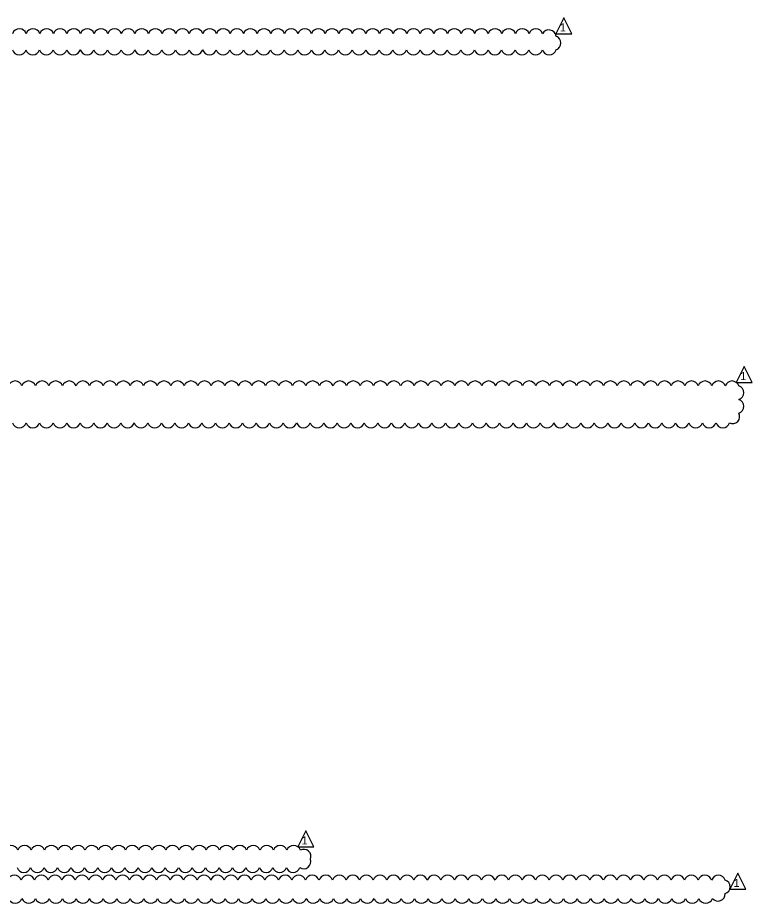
# Model space of a CAD drawing. Extents: x -156 to 77, y 0 to 24.
# Drawn here: x 64.1 to 76.95, y 1.25 to 16.74 of the extents above; entities that cross this region are included whole.
import ezdxf

# ---------------------------------------------------------------- set-up
doc = ezdxf.new("R2010")
doc.units = 0
doc.layers.add('SH_Text', color=7, linetype='Continuous')

msp = doc.modelspace()

# ---------------------------------------------------------------- linework, layer by layer
at = {"layer": 'SH_Text'}
for points in [[(73.654, 16.74), (73.514, 16.46), (73.794, 16.46)], [(76.807, 10.643), (76.667, 10.363), (76.947, 10.363)], [(69.139, 2.523), (68.999, 2.243), (69.279, 2.243)], [(76.692, 1.778), (76.552, 1.498), (76.832, 1.498)]]:
    msp.add_lwpolyline(points, close=True, dxfattribs=at)
for centre, radius, start, end in [((64.132, 16.423), 0.125, 17.5, 162.5), ((64.369, 16.423), 0.125, 17.5, 162.5), ((64.607, 16.423), 0.125, 17.5, 162.5), ((64.844, 16.423), 0.125, 17.5, 162.5), ((65.082, 16.423), 0.125, 17.5, 162.5), ((65.32, 16.423), 0.125, 17.5, 162.5), ((65.557, 16.423), 0.125, 17.5, 162.5), ((65.795, 16.423), 0.125, 17.5, 162.5), ((66.033, 16.423), 0.125, 17.5, 162.5), ((66.27, 16.423), 0.125, 17.5, 162.5), ((66.508, 16.423), 0.125, 17.5, 162.5), ((66.746, 16.423), 0.125, 17.5, 162.5), ((66.983, 16.423), 0.125, 17.5, 162.5), ((67.221, 16.423), 0.125, 17.5, 162.5), ((67.458, 16.423), 0.125, 17.5, 162.5), ((67.696, 16.423), 0.125, 17.5, 162.5), ((67.934, 16.423), 0.125, 17.5, 162.5), ((68.171, 16.423), 0.125, 17.5, 162.5), ((68.409, 16.423), 0.125, 17.5, 162.5), ((68.647, 16.423), 0.125, 17.5, 162.5), ((68.884, 16.423), 0.125, 17.5, 162.5), ((69.122, 16.423), 0.125, 17.5, 162.5), ((69.36, 16.423), 0.125, 17.5, 162.5), ((69.597, 16.423), 0.125, 17.5, 162.5), ((69.835, 16.423), 0.125, 17.5, 162.5), ((70.072, 16.423), 0.125, 17.5, 162.5), ((70.31, 16.423), 0.125, 17.5, 162.5), ((70.548, 16.423), 0.125, 17.5, 162.5), ((70.785, 16.423), 0.125, 17.5, 162.5), ((71.023, 16.423), 0.125, 17.5, 162.5), ((71.261, 16.423), 0.125, 17.5, 162.5), ((71.498, 16.423), 0.125, 17.5, 162.5), ((71.736, 16.423), 0.125, 17.5, 162.5), ((71.974, 16.423), 0.125, 17.5, 162.5), ((72.211, 16.423), 0.125, 17.5, 162.5), ((72.449, 16.423), 0.125, 17.5, 162.5), ((72.686, 16.423), 0.125, 17.5, 162.5), ((72.924, 16.423), 0.125, 17.5, 162.5), ((73.162, 16.423), 0.125, 17.5, 162.5), ((73.391, 16.402), 0.125, 7.2291, 152.2291), ((73.477, 16.299), 0.125, 287.5, 72.5), ((64.128, 16.217), 0.125, 197.5, 342.5), ((64.365, 16.217), 0.125, 197.5, 342.5), ((64.603, 16.217), 0.125, 197.5, 342.5), ((64.841, 16.217), 0.125, 197.5, 342.5), ((65.078, 16.217), 0.125, 197.5, 342.5), ((65.316, 16.217), 0.125, 197.5, 342.5), ((65.554, 16.217), 0.125, 197.5, 342.5), ((65.791, 16.217), 0.125, 197.5, 342.5), ((66.029, 16.217), 0.125, 197.5, 342.5), ((66.266, 16.217), 0.125, 197.5, 342.5), ((66.504, 16.217), 0.125, 197.5, 342.5), ((66.742, 16.217), 0.125, 197.5, 342.5), ((66.979, 16.217), 0.125, 197.5, 342.5), ((67.217, 16.217), 0.125, 197.5, 342.5), ((67.455, 16.217), 0.125, 197.5, 342.5), ((67.692, 16.217), 0.125, 197.5, 342.5), ((67.93, 16.217), 0.125, 197.5, 342.5), ((68.168, 16.217), 0.125, 197.5, 342.5), ((68.405, 16.217), 0.125, 197.5, 342.5), ((68.643, 16.217), 0.125, 197.5, 342.5), ((68.88, 16.217), 0.125, 197.5, 342.5), ((69.118, 16.217), 0.125, 197.5, 342.5), ((69.356, 16.217), 0.125, 197.5, 342.5), ((69.593, 16.217), 0.125, 197.5, 342.5), ((69.831, 16.217), 0.125, 197.5, 342.5), ((70.069, 16.217), 0.125, 197.5, 342.5), ((70.306, 16.217), 0.125, 197.5, 342.5), ((70.544, 16.217), 0.125, 197.5, 342.5), ((70.782, 16.217), 0.125, 197.5, 342.5), ((71.019, 16.217), 0.125, 197.5, 342.5), ((71.257, 16.217), 0.125, 197.5, 342.5), ((71.494, 16.217), 0.125, 197.5, 342.5), ((71.732, 16.217), 0.125, 197.5, 342.5), ((71.97, 16.217), 0.125, 197.5, 342.5), ((72.207, 16.217), 0.125, 197.5, 342.5), ((72.445, 16.217), 0.125, 197.5, 342.5), ((72.683, 16.217), 0.125, 197.5, 342.5), ((72.92, 16.217), 0.125, 197.5, 342.5), ((73.158, 16.217), 0.125, 197.5, 342.5), ((73.396, 16.217), 0.125, 197.5, 342.5), ((64.057, 10.263), 0.124, 17.5, 162.5), ((64.293, 10.263), 0.124, 17.5, 162.5), ((64.53, 10.263), 0.124, 17.5, 162.5), ((64.766, 10.263), 0.124, 17.5, 162.5), ((65.003, 10.263), 0.124, 17.5, 162.5), ((65.24, 10.263), 0.124, 17.5, 162.5), ((65.476, 10.263), 0.124, 17.5, 162.5), ((65.713, 10.263), 0.124, 17.5, 162.5), ((65.949, 10.263), 0.124, 17.5, 162.5), ((66.186, 10.263), 0.124, 17.5, 162.5), ((66.422, 10.263), 0.124, 17.5, 162.5), ((66.659, 10.263), 0.124, 17.5, 162.5), ((66.895, 10.263), 0.124, 17.5, 162.5), ((67.132, 10.263), 0.124, 17.5, 162.5), ((67.368, 10.263), 0.124, 17.5, 162.5), ((67.605, 10.263), 0.124, 17.5, 162.5), ((67.842, 10.263), 0.124, 17.5, 162.5), ((68.078, 10.263), 0.124, 17.5, 162.5), ((68.315, 10.263), 0.124, 17.5, 162.5), ((68.551, 10.263), 0.124, 17.5, 162.5), ((68.788, 10.263), 0.124, 17.5, 162.5), ((69.024, 10.263), 0.124, 17.5, 162.5), ((69.261, 10.263), 0.124, 17.5, 162.5), ((69.497, 10.263), 0.124, 17.5, 162.5), ((69.734, 10.263), 0.124, 17.5, 162.5), ((69.97, 10.263), 0.124, 17.5, 162.5), ((70.207, 10.263), 0.124, 17.5, 162.5), ((70.443, 10.263), 0.124, 17.5, 162.5), ((70.68, 10.263), 0.124, 17.5, 162.5), ((70.917, 10.263), 0.124, 17.5, 162.5), ((71.153, 10.263), 0.124, 17.5, 162.5), ((71.39, 10.263), 0.124, 17.5, 162.5), ((71.626, 10.263), 0.124, 17.5, 162.5), ((71.863, 10.263), 0.124, 17.5, 162.5), ((72.099, 10.263), 0.124, 17.5, 162.5), ((72.336, 10.263), 0.124, 17.5, 162.5), ((72.572, 10.263), 0.124, 17.5, 162.5), ((72.809, 10.263), 0.124, 17.5, 162.5), ((73.045, 10.263), 0.124, 17.5, 162.5), ((73.282, 10.263), 0.124, 17.5, 162.5), ((73.519, 10.263), 0.124, 17.5, 162.5), ((73.755, 10.263), 0.124, 17.5, 162.5), ((73.992, 10.263), 0.124, 17.5, 162.5), ((74.228, 10.263), 0.124, 17.5, 162.5), ((74.465, 10.263), 0.124, 17.5, 162.5), ((74.701, 10.263), 0.124, 17.5, 162.5), ((74.938, 10.263), 0.124, 17.5, 162.5), ((75.174, 10.263), 0.124, 17.5, 162.5), ((75.411, 10.263), 0.124, 17.5, 162.5), ((75.647, 10.263), 0.124, 17.5, 162.5), ((75.884, 10.263), 0.124, 17.5, 162.5), ((76.121, 10.263), 0.124, 17.5, 162.5), ((76.357, 10.263), 0.124, 17.5, 162.5), ((76.594, 10.263), 0.124, 17.5, 162.5), ((76.675, 10.182), 0.124, 287.5, 72.5), ((76.675, 9.945), 0.124, 287.5, 72.5), ((76.603, 9.767), 0.124, 243.9222, 28.9222), ((64.13, 9.693), 0.124, 197.5, 342.5), ((64.367, 9.693), 0.124, 197.5, 342.5), ((64.603, 9.693), 0.124, 197.5, 342.5), ((64.84, 9.693), 0.124, 197.5, 342.5), ((65.077, 9.693), 0.124, 197.5, 342.5), ((65.313, 9.693), 0.124, 197.5, 342.5), ((65.55, 9.693), 0.124, 197.5, 342.5), ((65.786, 9.693), 0.124, 197.5, 342.5), ((66.023, 9.693), 0.124, 197.5, 342.5), ((66.259, 9.693), 0.124, 197.5, 342.5), ((66.496, 9.693), 0.124, 197.5, 342.5), ((66.732, 9.693), 0.124, 197.5, 342.5), ((66.969, 9.693), 0.124, 197.5, 342.5), ((67.205, 9.693), 0.124, 197.5, 342.5), ((67.442, 9.693), 0.124, 197.5, 342.5), ((67.679, 9.693), 0.124, 197.5, 342.5), ((67.915, 9.693), 0.124, 197.5, 342.5), ((68.152, 9.693), 0.124, 197.5, 342.5), ((68.388, 9.693), 0.124, 197.5, 342.5), ((68.625, 9.693), 0.124, 197.5, 342.5), ((68.861, 9.693), 0.124, 197.5, 342.5), ((69.098, 9.693), 0.124, 197.5, 342.5), ((69.334, 9.693), 0.124, 197.5, 342.5), ((69.571, 9.693), 0.124, 197.5, 342.5), ((69.807, 9.693), 0.124, 197.5, 342.5), ((70.044, 9.693), 0.124, 197.5, 342.5), ((70.281, 9.693), 0.124, 197.5, 342.5), ((70.517, 9.693), 0.124, 197.5, 342.5), ((70.754, 9.693), 0.124, 197.5, 342.5), ((70.99, 9.693), 0.124, 197.5, 342.5), ((71.227, 9.693), 0.124, 197.5, 342.5), ((71.463, 9.693), 0.124, 197.5, 342.5), ((71.7, 9.693), 0.124, 197.5, 342.5), ((71.936, 9.693), 0.124, 197.5, 342.5), ((72.173, 9.693), 0.124, 197.5, 342.5), ((72.409, 9.693), 0.124, 197.5, 342.5), ((72.646, 9.693), 0.124, 197.5, 342.5), ((72.882, 9.693), 0.124, 197.5, 342.5), ((73.119, 9.693), 0.124, 197.5, 342.5), ((73.356, 9.693), 0.124, 197.5, 342.5), ((73.592, 9.693), 0.124, 197.5, 342.5), ((73.829, 9.693), 0.124, 197.5, 342.5), ((74.065, 9.693), 0.124, 197.5, 342.5), ((74.302, 9.693), 0.124, 197.5, 342.5), ((74.538, 9.693), 0.124, 197.5, 342.5), ((74.775, 9.693), 0.124, 197.5, 342.5), ((75.011, 9.693), 0.124, 197.5, 342.5), ((75.248, 9.693), 0.124, 197.5, 342.5), ((75.484, 9.693), 0.124, 197.5, 342.5), ((75.721, 9.693), 0.124, 197.5, 342.5), ((75.958, 9.693), 0.124, 197.5, 342.5), ((76.194, 9.693), 0.124, 197.5, 342.5), ((76.431, 9.693), 0.124, 197.5, 342.5), ((63.984, 2.143), 0.123, 17.5, 162.5), ((64.22, 2.143), 0.123, 17.5, 162.5), ((64.455, 2.143), 0.123, 17.5, 162.5), ((64.69, 2.143), 0.123, 17.5, 162.5), ((64.926, 2.143), 0.123, 17.5, 162.5), ((65.161, 2.143), 0.123, 17.5, 162.5), ((65.396, 2.143), 0.123, 17.5, 162.5), ((65.632, 2.143), 0.123, 17.5, 162.5), ((65.867, 2.143), 0.123, 17.5, 162.5), ((66.103, 2.143), 0.123, 17.5, 162.5), ((66.338, 2.143), 0.123, 17.5, 162.5), ((66.573, 2.143), 0.123, 17.5, 162.5), ((66.809, 2.143), 0.123, 17.5, 162.5), ((67.044, 2.143), 0.123, 17.5, 162.5), ((67.279, 2.143), 0.123, 17.5, 162.5), ((67.515, 2.143), 0.123, 17.5, 162.5), ((67.75, 2.143), 0.123, 17.5, 162.5), ((67.986, 2.143), 0.123, 17.5, 162.5), ((68.221, 2.143), 0.123, 17.5, 162.5), ((68.456, 2.143), 0.123, 17.5, 162.5), ((68.692, 2.143), 0.123, 17.5, 162.5), ((68.927, 2.143), 0.123, 17.5, 162.5), ((69.107, 2.074), 0.123, 335.435, 120.435), ((69.104, 1.979), 0.123, 235.8086, 20.8086), ((64.209, 1.914), 0.123, 197.5, 342.5), ((64.445, 1.914), 0.123, 197.5, 342.5), ((64.68, 1.914), 0.123, 197.5, 342.5), ((64.916, 1.914), 0.123, 197.5, 342.5), ((65.151, 1.914), 0.123, 197.5, 342.5), ((65.386, 1.914), 0.123, 197.5, 342.5), ((65.622, 1.914), 0.123, 197.5, 342.5), ((65.857, 1.914), 0.123, 197.5, 342.5), ((66.092, 1.914), 0.123, 197.5, 342.5), ((66.328, 1.914), 0.123, 197.5, 342.5), ((66.563, 1.914), 0.123, 197.5, 342.5), ((66.799, 1.914), 0.123, 197.5, 342.5), ((67.034, 1.914), 0.123, 197.5, 342.5), ((67.269, 1.914), 0.123, 197.5, 342.5), ((67.505, 1.914), 0.123, 197.5, 342.5), ((67.74, 1.914), 0.123, 197.5, 342.5), ((67.976, 1.914), 0.123, 197.5, 342.5), ((68.211, 1.914), 0.123, 197.5, 342.5), ((68.446, 1.914), 0.123, 197.5, 342.5), ((68.682, 1.914), 0.123, 197.5, 342.5), ((68.917, 1.914), 0.123, 197.5, 342.5), ((64.043, 1.622), 0.124, 17.5, 162.5), ((64.28, 1.622), 0.124, 17.5, 162.5), ((64.516, 1.622), 0.124, 17.5, 162.5), ((64.753, 1.622), 0.124, 17.5, 162.5), ((64.99, 1.622), 0.124, 17.5, 162.5), ((65.227, 1.622), 0.124, 17.5, 162.5), ((65.464, 1.622), 0.124, 17.5, 162.5), ((65.7, 1.622), 0.124, 17.5, 162.5), ((65.937, 1.622), 0.124, 17.5, 162.5), ((66.174, 1.622), 0.124, 17.5, 162.5), ((66.411, 1.622), 0.124, 17.5, 162.5), ((66.647, 1.622), 0.124, 17.5, 162.5), ((66.884, 1.622), 0.124, 17.5, 162.5), ((67.121, 1.622), 0.124, 17.5, 162.5), ((67.358, 1.622), 0.124, 17.5, 162.5), ((67.594, 1.622), 0.124, 17.5, 162.5), ((67.831, 1.622), 0.124, 17.5, 162.5), ((68.068, 1.622), 0.124, 17.5, 162.5), ((68.305, 1.622), 0.124, 17.5, 162.5), ((68.542, 1.622), 0.124, 17.5, 162.5), ((68.778, 1.622), 0.124, 17.5, 162.5), ((69.015, 1.622), 0.124, 17.5, 162.5), ((69.252, 1.622), 0.124, 17.5, 162.5), ((69.489, 1.622), 0.124, 17.5, 162.5), ((69.725, 1.622), 0.124, 17.5, 162.5), ((69.962, 1.622), 0.124, 17.5, 162.5), ((70.199, 1.622), 0.124, 17.5, 162.5), ((70.436, 1.622), 0.124, 17.5, 162.5), ((70.673, 1.622), 0.124, 17.5, 162.5), ((70.909, 1.622), 0.124, 17.5, 162.5), ((71.146, 1.622), 0.124, 17.5, 162.5), ((71.383, 1.622), 0.124, 17.5, 162.5), ((71.62, 1.622), 0.124, 17.5, 162.5), ((71.856, 1.622), 0.124, 17.5, 162.5), ((72.093, 1.622), 0.124, 17.5, 162.5), ((72.33, 1.622), 0.124, 17.5, 162.5), ((72.567, 1.622), 0.124, 17.5, 162.5), ((72.803, 1.622), 0.124, 17.5, 162.5), ((73.04, 1.622), 0.124, 17.5, 162.5), ((73.277, 1.622), 0.124, 17.5, 162.5), ((73.514, 1.622), 0.124, 17.5, 162.5), ((73.751, 1.622), 0.124, 17.5, 162.5), ((73.987, 1.622), 0.124, 17.5, 162.5), ((74.224, 1.622), 0.124, 17.5, 162.5), ((74.461, 1.622), 0.124, 17.5, 162.5), ((74.698, 1.622), 0.124, 17.5, 162.5), ((74.934, 1.622), 0.124, 17.5, 162.5), ((75.171, 1.622), 0.124, 17.5, 162.5), ((75.408, 1.622), 0.124, 17.5, 162.5), ((75.645, 1.622), 0.124, 17.5, 162.5), ((75.882, 1.622), 0.124, 17.5, 162.5), ((76.118, 1.622), 0.124, 17.5, 162.5), ((76.355, 1.622), 0.124, 17.5, 162.5), ((76.436, 1.541), 0.124, 287.5, 72.5), ((76.349, 1.416), 0.124, 217.9714, 2.9714), ((64.058, 1.377), 0.124, 197.5, 342.5), ((64.295, 1.377), 0.124, 197.5, 342.5), ((64.531, 1.377), 0.124, 197.5, 342.5), ((64.768, 1.377), 0.124, 197.5, 342.5), ((65.005, 1.377), 0.124, 197.5, 342.5), ((65.242, 1.377), 0.124, 197.5, 342.5), ((65.478, 1.377), 0.124, 197.5, 342.5), ((65.715, 1.377), 0.124, 197.5, 342.5), ((65.952, 1.377), 0.124, 197.5, 342.5), ((66.189, 1.377), 0.124, 197.5, 342.5), ((66.426, 1.377), 0.124, 197.5, 342.5), ((66.662, 1.377), 0.124, 197.5, 342.5), ((66.899, 1.377), 0.124, 197.5, 342.5), ((67.136, 1.377), 0.124, 197.5, 342.5), ((67.373, 1.377), 0.124, 197.5, 342.5), ((67.609, 1.377), 0.124, 197.5, 342.5), ((67.846, 1.377), 0.124, 197.5, 342.5), ((68.083, 1.377), 0.124, 197.5, 342.5), ((68.32, 1.377), 0.124, 197.5, 342.5), ((68.557, 1.377), 0.124, 197.5, 342.5), ((68.793, 1.377), 0.124, 197.5, 342.5), ((69.03, 1.377), 0.124, 197.5, 342.5), ((69.267, 1.377), 0.124, 197.5, 342.5), ((69.504, 1.377), 0.124, 197.5, 342.5), ((69.74, 1.377), 0.124, 197.5, 342.5), ((69.977, 1.377), 0.124, 197.5, 342.5), ((70.214, 1.377), 0.124, 197.5, 342.5), ((70.451, 1.377), 0.124, 197.5, 342.5), ((70.687, 1.377), 0.124, 197.5, 342.5), ((70.924, 1.377), 0.124, 197.5, 342.5), ((71.161, 1.377), 0.124, 197.5, 342.5), ((71.398, 1.377), 0.124, 197.5, 342.5), ((71.635, 1.377), 0.124, 197.5, 342.5), ((71.871, 1.377), 0.124, 197.5, 342.5), ((72.108, 1.377), 0.124, 197.5, 342.5), ((72.345, 1.377), 0.124, 197.5, 342.5), ((72.582, 1.377), 0.124, 197.5, 342.5), ((72.818, 1.377), 0.124, 197.5, 342.5), ((73.055, 1.377), 0.124, 197.5, 342.5), ((73.292, 1.377), 0.124, 197.5, 342.5), ((73.529, 1.377), 0.124, 197.5, 342.5), ((73.766, 1.377), 0.124, 197.5, 342.5), ((74.002, 1.377), 0.124, 197.5, 342.5), ((74.239, 1.377), 0.124, 197.5, 342.5), ((74.476, 1.377), 0.124, 197.5, 342.5), ((74.713, 1.377), 0.124, 197.5, 342.5), ((74.949, 1.377), 0.124, 197.5, 342.5), ((75.186, 1.377), 0.124, 197.5, 342.5), ((75.423, 1.377), 0.124, 197.5, 342.5), ((75.66, 1.377), 0.124, 197.5, 342.5), ((75.896, 1.377), 0.124, 197.5, 342.5), ((76.133, 1.377), 0.124, 197.5, 342.5)]:
    msp.add_arc(centre, radius, start, end, dxfattribs=at)

# ---------------------------------------------------------------- texts
for p in [(73.583, 16.5), (76.736, 10.403), (69.067, 2.283), (76.621, 1.538)]:
    msp.add_text('1', height=0.14, dxfattribs=at).set_placement(p)

doc.saveas('drawing.dxf')
